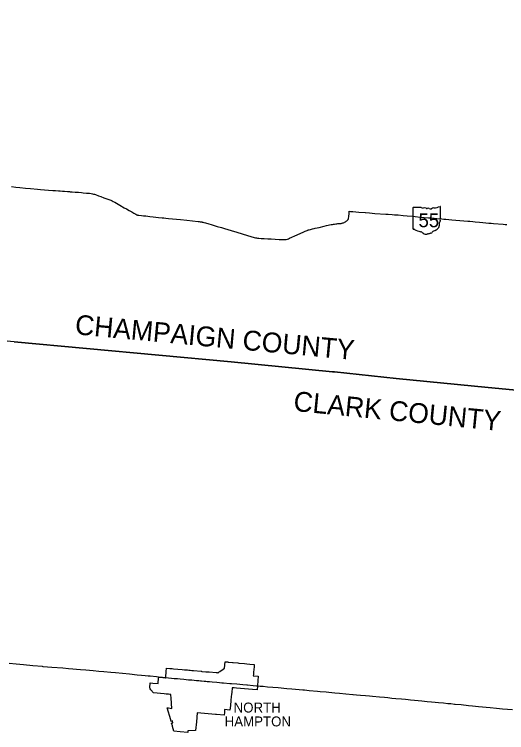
# Model space of a CAD drawing. Extents: x 0 to 34, y 0 to 22.
# Drawn here: x 6.29 to 6.689, y 16.46 to 17.041 of the extents above; entities that cross this region are included whole.
import ezdxf

# ---------------------------------------------------------------- set-up
doc = ezdxf.new("R2010")
doc.units = 0
for name, color, linetype in [('GM_X_Corporation', 7, 'Continuous'), ('GM_X_Corporation_Text', 7, 'Continuous'), ('GM_X_County', 7, 'Continuous'), ('GM_X_County_Text', 7, 'Continuous'), ('GM_X_State_Location', 7, 'Continuous'), ('GM_X_State_Route', 7, 'Continuous'), ('GM_X_State_Shield', 7, 'Continuous')]:
    doc.layers.add(name, color=color, linetype=linetype)

msp = doc.modelspace()

# ---------------------------------------------------------------- linework, layer by layer
at = {"layer": 'GM_X_Corporation'}
msp.add_lwpolyline([(6.41354, 16.51224), (6.41612, 16.512), (6.41627, 16.51199), (6.41819, 16.51181), (6.41915, 16.51172), (6.42616, 16.51107), (6.428, 16.5109), (6.42825, 16.51088), (6.42931, 16.51078), (6.43036, 16.51069), (6.43152, 16.51058), (6.43272, 16.51047), (6.4339, 16.51036), (6.43522, 16.51024), (6.44152, 16.50961), (6.44178, 16.50959), (6.44205, 16.50956), (6.44529, 16.50929), (6.44812, 16.50906), (6.44812, 16.50906), (6.45366, 16.50859), (6.45439, 16.50853), (6.45494, 16.50849), (6.45538, 16.50845), (6.45557, 16.50861), (6.45614, 16.50911), (6.45661, 16.50952), (6.45779, 16.51014), (6.45834, 16.51055), (6.46044, 16.51212), (6.46089, 16.51731), (6.46207, 16.51721), (6.46287, 16.51714), (6.46337, 16.5171), (6.46368, 16.51707), (6.46409, 16.51703), (6.46687, 16.51675), (6.46716, 16.51672), (6.46744, 16.51669), (6.47129, 16.51633), (6.47201, 16.51626), (6.47668, 16.51582), (6.4786, 16.51563), (6.48106, 16.5154), (6.48455, 16.51507), (6.48438, 16.51332), (6.4842, 16.51116), (6.48401, 16.509), (6.48384, 16.50704), (6.48375, 16.50599), (6.48737, 16.50567), (6.48779, 16.50563), (6.48723, 16.49809), (6.48719, 16.49762), (6.48691, 16.49456), (6.483, 16.49491), (6.47333, 16.49577), (6.47009, 16.49606), (6.46817, 16.49623), (6.46673, 16.49635), (6.46662, 16.49533), (6.46658, 16.49489), (6.46648, 16.49392), (6.46643, 16.49346), (6.46641, 16.49326), (6.46635, 16.49274), (6.46626, 16.49189), (6.46622, 16.49142), (6.46592, 16.48855), (6.46569, 16.4864), (6.46554, 16.48494), (6.46546, 16.48418), (6.46538, 16.48342), (6.46528, 16.4824), (6.46521, 16.48179), (6.46485, 16.47824), (6.46272, 16.47843), (6.46054, 16.47863), (6.46034, 16.47637), (6.46015, 16.47411), (6.45396, 16.47462), (6.45378, 16.47464), (6.45341, 16.47467), (6.45305, 16.4747), (6.43842, 16.4759), (6.43771, 16.46882), (6.43701, 16.46173), (6.43089, 16.46142), (6.43087, 16.45996), (6.42445, 16.46059), (6.41953, 16.46108), (6.4184, 16.46501), (6.41832, 16.46529), (6.41825, 16.46552), (6.41765, 16.46763), (6.41808, 16.46776), (6.41873, 16.46794), (6.4183, 16.46941), (6.41789, 16.46929), (6.41722, 16.4691), (6.41688, 16.47029), (6.41408, 16.48003), (6.41511, 16.47991), (6.41791, 16.47957), (6.41729, 16.48784), (6.4171, 16.49047), (6.41707, 16.49079), (6.41666, 16.49083), (6.41608, 16.49089), (6.41508, 16.49099), (6.41408, 16.49108), (6.41309, 16.49118), (6.41147, 16.49134), (6.40286, 16.49217), (6.40082, 16.49471), (6.40016, 16.49554), (6.39987, 16.49619), (6.40024, 16.50025), (6.40253, 16.50002), (6.40663, 16.49961), (6.40712, 16.50442), (6.40717, 16.5049), (6.41059, 16.50457), (6.41272, 16.50436), (6.41283, 16.50435), (6.41287, 16.50483), (6.41328, 16.50933)], close=True, dxfattribs=at)
at = {"layer": 'GM_X_County'}
for points in [[(6.71957, 16.73506), (6.6741, 16.73927), (6.59943, 16.74659), (6.54946, 16.75192), (6.54785, 16.7521), (6.46577, 16.75996), (6.29003, 16.77638), (6.25289, 16.77985), (6.2102, 16.78383), (6.19421, 16.7849), (6.10999, 16.79164), (6.06128, 16.79649), (6.06097, 16.79637), (6.03211, 16.7989), (6.04024, 16.89022), (6.04326, 16.92267), (6.05575, 17.06702)], [(6.29003, 16.77638), (6.46577, 16.75996), (6.54785, 16.7521), (6.54946, 16.75192), (6.59943, 16.74659), (6.6741, 16.73927), (6.71957, 16.73506)]]:
    msp.add_lwpolyline(points, dxfattribs=at)
at = {"layer": 'GM_X_State_Route'}
for points in [[(6.28786, 16.90193), (6.29145, 16.90154), (6.29472, 16.90121), (6.29942, 16.90075), (6.30333, 16.90035), (6.30895, 16.89979), (6.31141, 16.89957), (6.31458, 16.89932), (6.31788, 16.89905), (6.3213, 16.89879), (6.32356, 16.89864), (6.32603, 16.89847), (6.32737, 16.89838), (6.32913, 16.89823), (6.33093, 16.89809), (6.33341, 16.89791), (6.33482, 16.89781), (6.33535, 16.89776), (6.33708, 16.89763), (6.3394, 16.89747), (6.34113, 16.89734), (6.34219, 16.89726), (6.34475, 16.89705), (6.34612, 16.89693), (6.34879, 16.89666), (6.35111, 16.89646), (6.35261, 16.89626), (6.35351, 16.89611), (6.35443, 16.89589), (6.35526, 16.89566), (6.35612, 16.89539), (6.35854, 16.8945), (6.36037, 16.89383), (6.36273, 16.89293), (6.36522, 16.89198), (6.36834, 16.89079), (6.36939, 16.89034), (6.37029, 16.88991), (6.37158, 16.88922), (6.37312, 16.88836), (6.37426, 16.88773), (6.37582, 16.88683), (6.37933, 16.88479), (6.381, 16.88384), (6.38323, 16.88252), (6.38426, 16.88191), (6.3853, 16.88134), (6.38712, 16.88029), (6.38752, 16.88005), (6.38801, 16.87977), (6.38828, 16.87962), (6.38857, 16.87947), (6.38884, 16.87933), (6.38919, 16.87917), (6.38948, 16.87906), (6.38978, 16.87895), (6.38997, 16.8789), (6.39036, 16.8788), (6.39071, 16.87874), (6.3912, 16.87866), (6.39332, 16.87847), (6.3948, 16.87833), (6.39676, 16.87813), (6.3999, 16.87779), (6.40273, 16.87746), (6.40697, 16.87701), (6.40988, 16.87669), (6.41125, 16.87653), (6.41286, 16.87639), (6.41523, 16.87617), (6.42486, 16.87516), (6.43007, 16.87461), (6.43907, 16.87373), (6.43993, 16.87361), (6.44066, 16.8735), (6.44141, 16.87338), (6.44199, 16.87327), (6.44248, 16.87316), (6.44303, 16.87303), (6.44374, 16.87286), (6.44495, 16.87253), (6.44771, 16.87172), (6.4497, 16.87113), (6.45285, 16.87023), (6.4546, 16.86971), (6.45802, 16.86869), (6.46038, 16.86799), (6.46592, 16.86634), (6.47048, 16.86498), (6.47475, 16.86374), (6.47908, 16.86239), (6.48458, 16.86078), (6.48553, 16.86055), (6.48641, 16.86036), (6.48715, 16.86024), (6.48829, 16.8601), (6.49002, 16.85999), (6.49248, 16.85986), (6.49566, 16.85974), (6.49821, 16.8596), (6.5014, 16.85939), (6.50484, 16.85918), (6.50744, 16.85906), (6.50852, 16.85902), (6.50973, 16.85905), (6.51052, 16.85913), (6.51139, 16.85934), (6.51224, 16.85963), (6.51313, 16.86006), (6.5192, 16.8628), (6.52458, 16.86527), (6.52585, 16.86588), (6.5266, 16.86618), (6.52726, 16.86643), (6.52781, 16.86664), (6.52832, 16.86682), (6.52888, 16.86699), (6.52998, 16.86726), (6.53162, 16.86765), (6.53294, 16.86794), (6.53396, 16.86815), (6.53715, 16.86892), (6.54109, 16.86986), (6.54305, 16.87032), (6.54428, 16.8706), (6.54445, 16.87064)], [(6.56078, 16.87561), (6.56084, 16.8759), (6.56088, 16.87613), (6.56091, 16.87643), (6.56101, 16.87736), (6.56131, 16.88043), (6.56147, 16.88195)], [(6.56147, 16.88195), (6.5626, 16.88185), (6.5643, 16.88169), (6.56922, 16.88128), (6.57433, 16.88085)], [(6.57433, 16.88085), (6.57476, 16.88082), (6.578, 16.88057), (6.58222, 16.88024), (6.5911, 16.87956), (6.59303, 16.87946), (6.59632, 16.87929), (6.59821, 16.87917), (6.59936, 16.87909), (6.60115, 16.87891), (6.60508, 16.87854), (6.60845, 16.87824), (6.61275, 16.87787), (6.6149, 16.87766), (6.619, 16.87726), (6.62021, 16.87714), (6.6222, 16.87697), (6.62573, 16.87669), (6.62814, 16.87648), (6.63029, 16.87629), (6.63234, 16.87609), (6.63639, 16.87576), (6.63796, 16.87562), (6.6398, 16.87546), (6.64206, 16.87526), (6.64442, 16.87504), (6.65743, 16.87394), (6.65922, 16.87382), (6.66159, 16.8736), (6.66346, 16.87342), (6.66686, 16.87307), (6.66977, 16.87279), (6.67457, 16.87234), (6.6764, 16.87219), (6.67834, 16.87203), (6.68618, 16.87142), (6.6877, 16.87134), (6.68901, 16.87126)], [(6.54445, 16.87064), (6.54561, 16.87089), (6.54685, 16.87114), (6.54779, 16.87131), (6.54859, 16.87143), (6.54946, 16.87156), (6.55057, 16.87171), (6.55136, 16.8718), (6.55224, 16.8719), (6.55397, 16.87207), (6.55496, 16.87216), (6.55548, 16.87224), (6.55587, 16.87235), (6.55627, 16.87246), (6.55671, 16.8726), (6.55723, 16.8728), (6.55776, 16.87308), (6.55833, 16.87341), (6.55888, 16.87379), (6.55947, 16.87423), (6.56006, 16.87475), (6.5602, 16.87488), (6.56035, 16.87504), (6.56056, 16.87529), (6.56067, 16.87545), (6.56078, 16.87561)], [(6.39864, 16.5057), (6.39617, 16.50594), (6.39328, 16.50622), (6.38961, 16.50656), (6.38357, 16.50715), (6.3778, 16.50771), (6.37229, 16.50826), (6.36836, 16.50867), (6.36285, 16.50917), (6.35864, 16.50954), (6.35418, 16.50996), (6.34818, 16.5105), (6.34375, 16.5109), (6.34053, 16.51118), (6.33772, 16.51142), (6.33422, 16.51168), (6.32949, 16.51204), (6.32056, 16.51276), (6.31367, 16.51333), (6.31294, 16.51339), (6.30532, 16.51404), (6.29771, 16.51476), (6.29167, 16.51531), (6.28616, 16.5158)], [(6.40712, 16.50485), (6.40535, 16.50503), (6.40037, 16.50553), (6.39872, 16.50569), (6.39864, 16.5057)], [(6.41274, 16.50431), (6.41033, 16.50452), (6.40712, 16.50485)], [(6.44101, 16.50167), (6.43976, 16.50178), (6.43765, 16.50197), (6.43398, 16.5023), (6.43138, 16.50254), (6.42745, 16.5029), (6.42455, 16.50321), (6.42228, 16.50341), (6.42111, 16.50352), (6.41982, 16.50363), (6.41286, 16.5043), (6.41274, 16.50431)], [(6.45951, 16.50002), (6.45835, 16.50012), (6.45642, 16.5003), (6.45417, 16.50051), (6.4505, 16.50084), (6.44817, 16.50103), (6.44631, 16.50119), (6.44544, 16.50127), (6.44393, 16.5014), (6.44189, 16.50159), (6.44101, 16.50167)], [(6.48721, 16.49758), (6.48642, 16.49765), (6.48354, 16.49788), (6.479, 16.49829), (6.47857, 16.49834), (6.47536, 16.49863), (6.47046, 16.49906), (6.46625, 16.49945), (6.46471, 16.49958), (6.45951, 16.50002)], [(6.52514, 16.49421), (6.52381, 16.49434), (6.51488, 16.4951), (6.51094, 16.49546), (6.50385, 16.4961), (6.49519, 16.49686), (6.49178, 16.49717), (6.48941, 16.49737), (6.48721, 16.49758)], [(6.69379, 16.47835), (6.68565, 16.47905), (6.68062, 16.47956), (6.67569, 16.48005), (6.67246, 16.48035), (6.66934, 16.48065), (6.66618, 16.48095), (6.66125, 16.48144), (6.65801, 16.48175), (6.652, 16.48233), (6.64716, 16.4828), (6.64683, 16.48283), (6.64368, 16.48314), (6.64132, 16.4834), (6.63785, 16.48371), (6.63371, 16.48411), (6.63109, 16.48437), (6.6282, 16.48464), (6.6245, 16.48498), (6.62035, 16.48541), (6.61431, 16.48597), (6.61116, 16.48626), (6.60906, 16.48647), (6.60696, 16.48667), (6.60382, 16.48697), (6.59909, 16.48741), (6.59603, 16.48771), (6.59279, 16.488), (6.58994, 16.48828), (6.58602, 16.48867), (6.58024, 16.48918), (6.57788, 16.48942), (6.57473, 16.4897), (6.57053, 16.4901), (6.56738, 16.49039), (6.56475, 16.49064), (6.5645, 16.49067), (6.55872, 16.49118), (6.55371, 16.49164), (6.54991, 16.492), (6.54481, 16.49245), (6.54271, 16.49262), (6.53805, 16.49304), (6.53588, 16.49324), (6.52906, 16.49386), (6.52514, 16.49421)]]:
    msp.add_lwpolyline(points, dxfattribs=at)
at = {"layer": 'GM_X_State_Shield'}
for p, q in [((6.61307, 16.88481), (6.61307, 16.86782)), ((6.61984, 16.8851), (6.61329, 16.8851)), ((6.63545, 16.87664), (6.63545, 16.88552)), ((6.63544, 16.87664), (6.63545, 16.87664))]:
    msp.add_line(p, q, dxfattribs=at)
for centre, radius, start, end in [((6.61332, 16.88484), 0.000259, 98.1301, 188.1301), ((6.6214, 16.88707), 0.00251, 231.61951, 271.11188), ((6.62224, 16.87556), 0.00903, 80.48669, 94.98827), ((6.62429, 16.88493), 0.000725, 219.79206, 297.10237), ((6.62535, 16.88297), 0.00151, 54.46668, 119.14113), ((6.6273, 16.88566), 0.00181, 233.85621, 294.82819), ((6.6305, 16.87991), 0.00477, 97.34618, 120.76885), ((6.62747, 16.90825), 0.02373, 275.84447, 288.90645), ((6.6352, 16.88556), 0.000249, 351.86209, 97.738), ((6.63539, 16.87598), 0.000386, 107.94398, 210.33697), ((6.63518, 16.8766), 0.000267, 289.60381, 7.73413), ((6.6288, 16.87179), 0.00594, 292.30889, 8.98584), ((6.63634, 16.87292), 0.00168, 136.8065, 186.92959), ((6.63294, 16.87486), 0.00231, 340.03296, 23.64957), ((6.61333, 16.86779), 0.000262, 171.95839, 258.30661), ((6.61337, 16.86952), 0.002, 267.33899, 280.60386), ((6.61378, 16.86684), 0.00072, 29.74838, 93.27175), ((6.62286, 16.8821), 0.01714, 240.41292, 257.1985), ((6.61775, 16.86019), 0.00536, 47.18416, 75.83597), ((6.62741, 16.86384), 0.00051, 65.75173, 132.64842), ((6.62719, 16.86618), 0.00192, 282.87319, 323.27711), ((6.63131, 16.86305), 0.00325, 94.40312, 142.57675), ((6.62355, 16.86676), 0.0034, 230.70037, 286.29184), ((6.62552, 16.86089), 0.0028, 85.69512, 111.20995), ((6.62577, 16.86549), 0.00181, 268.77702, 315.54927)]:
    msp.add_arc(centre, radius, start, end, dxfattribs=at)

# ---------------------------------------------------------------- texts
at = {"layer": 'GM_X_Corporation_Text'}
for s, p in [('NORTH', (6.46782, 16.47623)), ('HAMPTON', (6.46058, 16.465))]:
    msp.add_text(s, height=0.008037, rotation=0.00001, dxfattribs=at).set_placement(p)
at = {"layer": 'GM_X_County_Text'}
for s, rotation, p in [('CHAMPAIGN COUNTY', 354.73971, (6.33893, 16.78239)), ('CLARK COUNTY', 354.44187, (6.51583, 16.7204))]:
    msp.add_text(s, height=0.016074, rotation=rotation, dxfattribs=at).set_placement(p)
at = {"layer": 'GM_X_State_Location'}
msp.add_text('55', height=0.0000161, rotation=0.00001, dxfattribs=at).set_placement((6.61996, 16.87402))
for s, p in [('s', (6.62401, 16.87519)), ('r', (6.624, 16.87519))]:
    msp.add_text(s, height=0.0000161, dxfattribs=at).set_placement(p)
at = {"layer": 'GM_X_State_Shield'}
msp.add_text('55', height=0.011189, dxfattribs=at).set_placement((6.61759, 16.86902))

doc.saveas('drawing.dxf')
